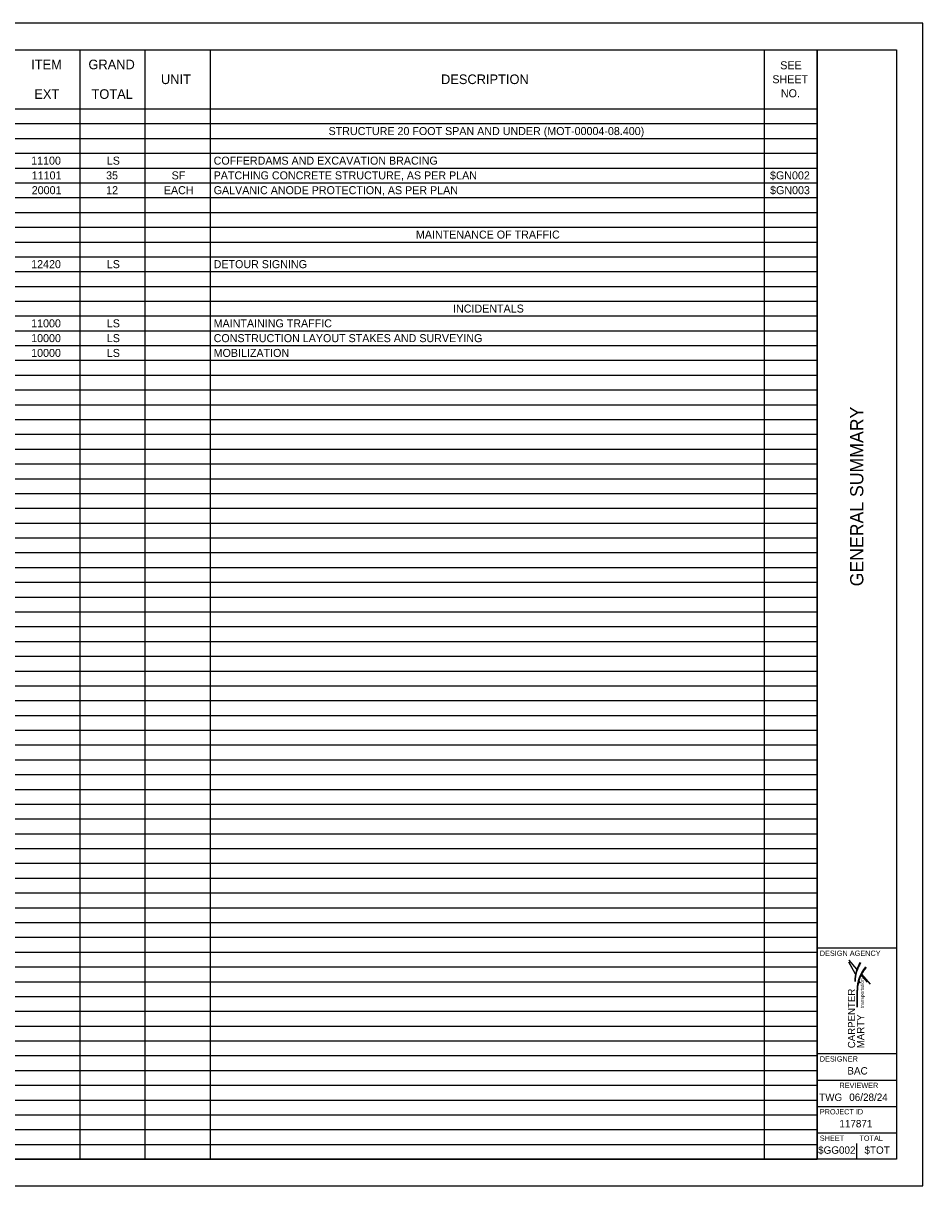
# Model space of a CAD drawing. Extents: x 0 to 34, y 0 to 22.
# Drawn here: x 16.96 to 34, y 0 to 22 of the extents above; entities that cross this region are included whole.
import ezdxf

# ---------------------------------------------------------------- set-up
doc = ezdxf.new("R2010")
doc.units = 0
for name, color, linetype in [('Default', 7, 'Continuous'), ('SH_Border', 7, 'Continuous'), ('SH_Cut_Line', 7, 'Continuous'), ('SH_Data', 7, 'Continuous'), ('SH_Text', 7, 'Continuous')]:
    doc.layers.add(name, color=color, linetype=linetype)

msp = doc.modelspace()

# ---------------------------------------------------------------- linework, layer by layer
at = {"layer": 'Default'}
for p, q in [((1.5, 21.5), (32, 21.5)), ((18.035, 21.5), (18.035, 0.502)), ((19.27, 21.5), (19.27, 0.502)), ((20.505, 21.5), (20.505, 0.502)), ((30.995, 21.5), (30.995, 0.502)), ((32, 21.5), (32, 0.502)), ((1.5, 20.38), (32, 20.38)), ((1.5, 20.1), (32, 20.1)), ((1.5, 19.82), (32, 19.82)), ((1.5, 19.54), (32, 19.54)), ((1.5, 19.26), (32, 19.26)), ((1.5, 18.98), (32, 18.98)), ((1.5, 18.7), (32, 18.7)), ((1.5, 18.42), (32, 18.42)), ((1.5, 18.14), (32, 18.14)), ((1.5, 17.86), (32, 17.86)), ((1.5, 17.58), (32, 17.58)), ((1.5, 17.3), (32, 17.3)), ((1.5, 17.021), (32, 17.021)), ((1.5, 16.741), (32, 16.741)), ((1.5, 16.461), (32, 16.461)), ((1.5, 16.181), (32, 16.181)), ((1.5, 15.901), (32, 15.901)), ((1.5, 15.621), (32, 15.621)), ((1.5, 15.341), (32, 15.341)), ((1.5, 15.061), (32, 15.061)), ((1.5, 14.781), (32, 14.781)), ((1.5, 14.501), (32, 14.501)), ((1.5, 14.221), (32, 14.221)), ((1.5, 13.941), (32, 13.941)), ((1.5, 13.661), (32, 13.661)), ((1.5, 13.381), (32, 13.381)), ((1.5, 13.101), (32, 13.101)), ((1.5, 12.821), (32, 12.821)), ((1.5, 12.541), (32, 12.541)), ((1.5, 12.261), (32, 12.261)), ((1.5, 11.981), (32, 11.981)), ((1.5, 11.701), (32, 11.701)), ((1.5, 11.421), (32, 11.421)), ((1.5, 11.141), (32, 11.141)), ((1.5, 10.861), (32, 10.861)), ((1.5, 10.581), (32, 10.581)), ((1.5, 10.301), (32, 10.301)), ((1.5, 10.021), (32, 10.021)), ((1.5, 9.741), (32, 9.741)), ((1.5, 9.461), (32, 9.461)), ((1.5, 9.181), (32, 9.181)), ((1.5, 8.901), (32, 8.901)), ((1.5, 8.621), (32, 8.621)), ((1.5, 8.342), (32, 8.342)), ((1.5, 8.062), (32, 8.062)), ((1.5, 7.782), (32, 7.782)), ((1.5, 7.502), (32, 7.502)), ((1.5, 7.222), (32, 7.222)), ((1.5, 6.942), (32, 6.942)), ((1.5, 6.662), (32, 6.662)), ((1.5, 6.382), (32, 6.382)), ((1.5, 6.102), (32, 6.102)), ((1.5, 5.822), (32, 5.822)), ((1.5, 5.542), (32, 5.542)), ((1.5, 5.262), (32, 5.262)), ((1.5, 4.982), (32, 4.982)), ((1.5, 4.702), (32, 4.702)), ((1.5, 4.422), (32, 4.422)), ((1.5, 4.142), (32, 4.142)), ((1.5, 3.862), (32, 3.862)), ((1.5, 3.582), (32, 3.582)), ((1.5, 3.302), (32, 3.302)), ((1.5, 3.022), (32, 3.022)), ((1.5, 2.742), (32, 2.742)), ((1.5, 2.462), (32, 2.462)), ((1.5, 2.182), (32, 2.182)), ((1.5, 1.902), (32, 1.902)), ((1.5, 1.622), (32, 1.622)), ((1.5, 1.342), (32, 1.342)), ((1.5, 1.062), (32, 1.062)), ((1.5, 0.782), (32, 0.782)), ((1.5, 0.502), (32, 0.502))]:
    msp.add_line(p, q, dxfattribs=at)
at = {"layer": 'SH_Border'}
for p, q in [((32, 0.5), (32, 21.5)), ((32, 4.5), (33.5, 4.5)), ((32, 2.5), (33.5, 2.5)), ((32, 2), (33.5, 2)), ((32, 1.5), (33.5, 1.5)), ((32, 1), (33.5, 1))]:
    msp.add_line(p, q, dxfattribs=at)
msp.add_lwpolyline([(1.5, 21.5), (33.5, 21.5), (33.5, 0.5), (1.5, 0.5)], close=True, dxfattribs=at)
at = {"layer": 'SH_Cut_Line'}
msp.add_lwpolyline([(0, 0), (34, 0), (34, 22), (0, 22)], close=True, dxfattribs=at)
at = {"layer": 'SH_Data'}
for p, q in [((32.75, 3.5), (32.75, 3.5)), ((32.375, 0.675), (32.375, 0.675)), ((32.75, 0.5), (32.75, 0.8))]:
    msp.add_line(p, q, dxfattribs=at)
at = {"layer": 'SH_Text'}
for p, q in [((32.721, 4.016), (32.602, 4.232)), ((32.952, 3.853), (32.834, 3.991)), ((32.839, 4.002), (33.006, 3.816)), ((32.811, 3.84), (32.79, 3.88)), ((32.82, 3.834), (32.791, 3.886)), ((32.755, 3.378), (32.755, 3.704)), ((32.762, 3.378), (32.762, 3.704))]:
    msp.add_line(p, q, dxfattribs=at)
for points in [[(32.746, 4.104), (32.601, 4.266)], [(32.601, 4.266), (32.744, 4.098)], [(32.721, 4.016), (32.602, 4.232)], [(32.602, 4.232), (32.719, 4.011)]]:
    msp.add_lwpolyline(points, dxfattribs=at)
for centre, radius, start, end in [((33.432, 3.86), 0.721, 149.5704, 179.5529), ((33.373, 3.862), 0.654, 147.1423, 179.6525), ((33.426, 3.704), 0.671, 139.2898, 180.0106), ((33.433, 3.688), 0.672, 138.5126, 178.6075)]:
    msp.add_arc(centre, radius, start, end, dxfattribs=at)

# ---------------------------------------------------------------- texts
at = {"layer": 'Default'}
for s, height, p in [('ITEM', 0.1818, (17.115, 21.129)), ('GRAND', 0.1818, (18.2, 21.129)), ('SEE ', 0.1515, (31.301, 21.129)), ('UNIT', 0.1818, (19.573, 20.849)), ('DESCRIPTION', 0.18181, (24.877, 20.849)), ('SHEET ', 0.1515, (31.152, 20.864)), ('EXT', 0.1818, (17.175, 20.569)), ('TOTAL', 0.1818, (18.258, 20.569)), ('NO.', 0.1515, (31.313, 20.599)), ('STRUCTURE 20 FOOT SPAN AND UNDER (MOT-00004-08.400)', 0.15151, (22.747, 19.884)), ('11100', 0.1515, (17.115, 19.324)), ('LS', 0.1515, (18.548, 19.324)), ('COFFERDAMS AND EXCAVATION BRACING', 0.15151, (20.571, 19.324)), ('11101', 0.1515, (17.126, 19.045)), ('35', 0.1515, (18.534, 19.045)), ('SF', 0.1515, (19.775, 19.045)), ('PATCHING CONCRETE STRUCTURE, AS PER PLAN', 0.15151, (20.571, 19.045)), ('$GN002', 0.1515, (31.107, 19.045)), ('$GN003', 0.1515, (31.108, 18.765)), ('20001', 0.1515, (17.126, 18.765)), ('12', 0.1515, (18.535, 18.765)), ('EACH', 0.1515, (19.628, 18.765)), ('GALVANIC ANODE PROTECTION, AS PER PLAN', 0.15151, (20.571, 18.765)), ('MAINTENANCE OF TRAFFIC', 0.15151, (24.402, 17.925)), ('12420', 0.1515, (17.115, 17.365)), ('LS', 0.1515, (18.548, 17.365)), ('DETOUR SIGNING', 0.15151, (20.571, 17.365)), ('INCIDENTALS', 0.15151, (25.105, 16.525)), ('11000', 0.1515, (17.115, 16.245)), ('LS', 0.1515, (18.548, 16.245)), ('MAINTAINING TRAFFIC', 0.15151, (20.571, 16.245)), ('10000', 0.1515, (17.115, 15.965)), ('LS', 0.1515, (18.548, 15.965)), ('CONSTRUCTION LAYOUT STAKES AND SURVEYING', 0.15151, (20.571, 15.965)), ('10000', 0.1515, (17.115, 15.685)), ('LS', 0.1515, (18.548, 15.685)), ('MOBILIZATION', 0.15151, (20.571, 15.685))]:
    msp.add_text(s, height=height, dxfattribs=at).set_placement(p)
at = {"layer": 'SH_Data'}
msp.add_text('GENERAL SUMMARY', height=0.25, rotation=90, dxfattribs=at).set_placement((32.875, 11.344))
for s, height, p in [('DESIGN AGENCY', 0.1, (32.05, 4.35)), ('DESIGNER', 0.1, (32.05, 2.35)), ('BAC', 0.14, (32.572, 2.105)), ('REVIEWER', 0.1, (32.422, 1.85)), ('TWG', 0.14, (32.038, 1.605)), ('06/28/24', 0.14, (32.608, 1.605)), ('PROJECT ID', 0.1, (32.05, 1.35)), ('117871', 0.14, (32.421, 1.105)), ('SHEET', 0.1, (32.05, 0.85)), ('TOTAL', 0.1, (32.8, 0.85)), ('$GG002', 0.14, (32.018, 0.605)), ('$TOT', 0.14, (32.896, 0.605))]:
    msp.add_text(s, height=height, dxfattribs=at).set_placement(p)
at = {"layer": 'SH_Text'}
for s, height, p in [('transportation', 0.06649, (32.885, 3.364)), ('CARPENTER ', 0.1367, (32.719, 2.602)), ('MARTY', 0.1367, (32.891, 2.602))]:
    msp.add_text(s, height=height, rotation=90, dxfattribs=at).set_placement(p)

doc.saveas('drawing.dxf')
